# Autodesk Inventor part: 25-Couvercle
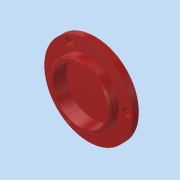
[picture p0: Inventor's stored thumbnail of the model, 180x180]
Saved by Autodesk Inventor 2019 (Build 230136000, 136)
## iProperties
Created: 2023-02
Part Number: 25-Couvercle
Material: Générique
Document SubType Name: Modeling
Designer: Thier
Density: 1 g/cm^3
Appearance: Rouge
Author: Thier
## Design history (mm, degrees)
sketch "Esquisse1"
  geometry: L1 (20, 0.706)-(20, -5.294); L2 (20, -5.294)-(29, -5.294); L3 (29, -5.294)-(29, -10.294); L4 (16.5, -13.294)-(0, -13.294); L5 (0, -13.294)-(0, -8.294); L6 (0, -8.294)-(17.5, -8.294); L7 (17.5, -8.294)-(17.5, 0.706); L8 (17.5, 0.706)-(20, 0.706); L9 (29, -10.294)-(16.5, -10.294); L10 (14.03, -4.706)-(14.03, -5.294); L11 (16.5, -10.294)-(16.5, -13.294); 2 further points
  constraints: 22 end point, 4 perpendicular, 3 vertical, 2 parallel, 1 horizontal, 1 midpoint, 1 point on line
  dimensions: "d0" = 35 diameter of L7 L5; "d1" = 58 diameter of L3 L5; "d2" = 40 diameter of L1 L5; "d4" = 6 distance of L1.start L1.end; "d6" = 9 distance of L6.end L7.end; "d7" = 33 diameter of L11 L5; "d8" = 14 distance between parallel lines of L8 L4
revolve "Révolution1" sketch "Esquisse1" stored, may be unused: angle "d9" = 90 deg
chamfer "Chanfrein1" distance "d10" = 3; stored, may be unused: second distance "d11" = 2, angle "d12" = 45 deg
sketch "Esquisse2"
  geometry: C1 r 29 at (0, 0) reference; 2 further points
  dimensions: "d20" = 0 vertical distance of C1.centre point (-25, 0); "d21" = 25 distance of C1.centre point (-25, 0)
hole "Perçage1" sketch "Esquisse2" at (-25, 0) diameter "d13" = 5.5; stored, may be unused: countersink angle "d17" = 90 deg, drill point angle "d19" = 118 deg; dims "d14" = 16, "d15" = 4, "d16" = 2, "d18" = 12
pattern_circular "Réseau circulaire1" dims angle "d23" = 360 deg
chamfer "Chanfrein2" distance "d25" = 1; stored, may be unused: second distance "d26" = 2, angle "d27" = 45 deg
node "Solide1"
